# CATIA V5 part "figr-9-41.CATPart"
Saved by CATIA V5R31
Part number: Part1
Bounding box of the stored display mesh (mm): x -40 to 40, y -20.616 to 191.034, z 0 to 131.022
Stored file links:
  D:\PROJECTS\Project 2021\US EDITION\CATIA V5 6R 2021\Resources\Part Files\c09_catia_v5_6r2021_prt\c09_catia_v5_6r2021_prt\figr-9-41.CATPart
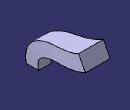
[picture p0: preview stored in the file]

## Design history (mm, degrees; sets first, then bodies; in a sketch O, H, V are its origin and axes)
Set1
  Plane1: type Normal, Curve Sketch2, RefPoint vertex of Sketch2
Body1 (main body)
  Sketch1 on xy-plane, origin (0, 0, 0), H (1, 0, 0), V (0, 1, 0)
    line L1 (20, 20) -> (20, -20)
    line L2 (20, -20) -> (-20, -20)
    line L3 (-20, -20) -> (-20, 20)
    line L4 (-20, 20) -> (20, 20)
    vertical: L1 V, L3 V
    horizontal: L2 H, L4 H
    equidistance: L1 L3 O, L2 L4 O
  Sketch2 on yz-plane, origin (0, 0, 0), H (0, 1, 0), V (0, 0, 1)
    spline S1 through (0, 0) (20, 60) (60, 80) (120, 90) (180, 110)
    point P1 (0, 0)
    coincidence: P1 O
  Sketch3 on Plane1, origin (0, 186.3865, 97.8327), H (1, 0, 0), V (0, -0.4648, 0.8854)
    point P1 (0, 13.7415)
    line L1 (40, 37.4831) -> (40, -10)
    line L2 (40, -10) -> (-40, -10)
    line L3 (-40, -10) -> (-40, 37.4831)
    line L4 (-40, 37.4831) -> (40, 37.4831)
    reference projected point E1 (0, 13.7415) from vertex of Sketch2
    coincidence: P1 V, P1 E1
    vertical: L1 V, L3 V
    horizontal: L2 H, L4 H
    equidistance: L1 L3 P1, L2 L4 P1
  Loft1: Sections (Sketch1; Sketch3), Spine Sketch2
